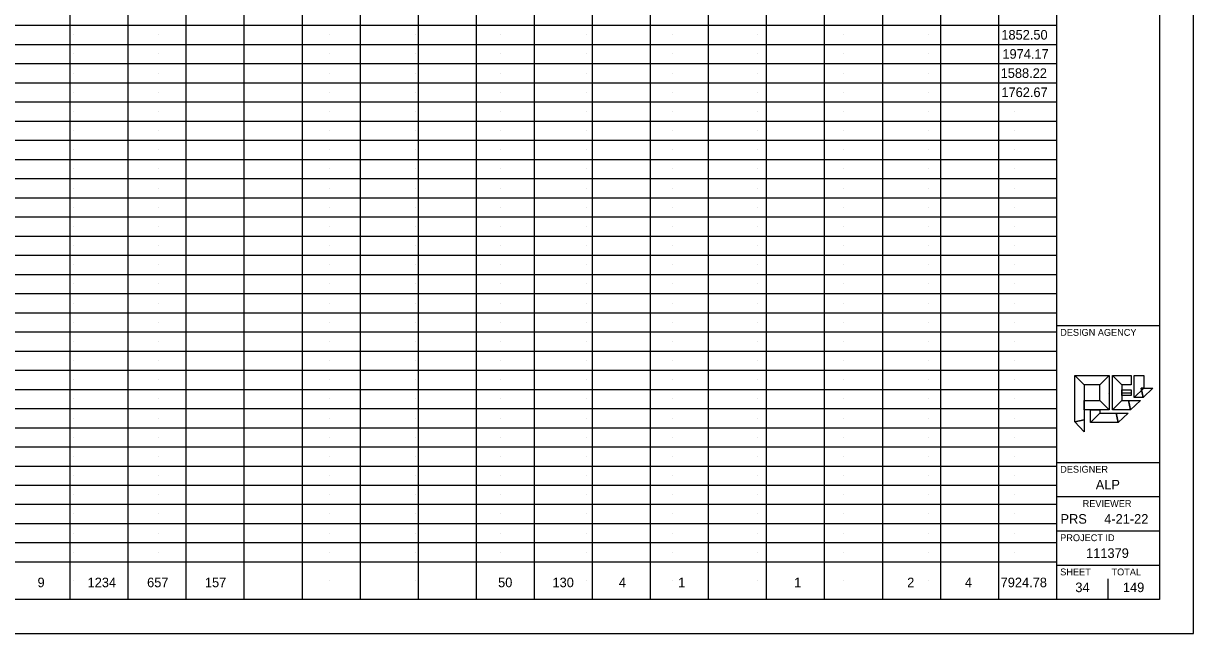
# Model space of a CAD drawing. Extents: x 2073163.9 to 2073197.9, y 634076.5 to 634098.5.
# Drawn here: x 2073180.84 to 2073197.95, y 634076.55 to 634085.46 of the extents above; entities that cross this region are included whole.
import ezdxf

# ---------------------------------------------------------------- set-up
doc = ezdxf.new("R2010")
doc.units = 0
for name, color, linetype in [('Default', 7, 'Continuous'), ('SH_Border', 7, 'Continuous'), ('SH_Cut_Line', 7, 'Continuous'), ('SH_Data', 7, 'Continuous'), ('SH_Text', 7, 'Continuous')]:
    doc.layers.add(name, color=color, linetype=linetype)

msp = doc.modelspace()

# ---------------------------------------------------------------- linework, layer by layer
at = {"layer": 'Default'}
msp.add_line((2073196.896, 634080.068), (2073197.032, 634080.068), dxfattribs=at)
for points in [[(2073196.209, 634079.643), (2073196.209, 634080.32), (2073196.347, 634080.183), (2073196.347, 634079.671)], [(2073196.209, 634080.32), (2073196.712, 634080.32), (2073196.576, 634080.183), (2073196.347, 634080.183)], [(2073196.712, 634080.32), (2073196.712, 634079.817), (2073196.576, 634079.954), (2073196.576, 634080.183)], [(2073196.758, 634079.817), (2073196.758, 634080.32), (2073196.896, 634080.183), (2073196.896, 634079.954)], [(2073196.758, 634080.32), (2073197.032, 634080.32), (2073197.032, 634080.183), (2073196.896, 634080.183)], [(2073197.078, 634080), (2073197.078, 634080.32), (2073197.216, 634080.32), (2073197.216, 634080.137)], [(2073197.032, 634080.11), (2073197.032, 634080.026), (2073196.897, 634080.026), (2073196.897, 634080.11)], [(2073197.207, 634080), (2073197.078, 634080), (2073197.216, 634080.137), (2073197.179, 634080.137)], [(2073197.352, 634080.137), (2073197.207, 634080), (2073197.179, 634080.137)], [(2073196.712, 634079.817), (2073196.347, 634079.817), (2073196.347, 634079.954), (2073196.576, 634079.954)], [(2073197.024, 634079.817), (2073196.758, 634079.817), (2073196.896, 634079.954), (2073196.996, 634079.954)], [(2073197.169, 634079.954), (2073197.024, 634079.817), (2073196.996, 634079.954)], [(2073196.347, 634079.497), (2073196.209, 634079.643), (2073196.347, 634079.671)], [(2073196.438, 634079.634), (2073196.438, 634079.817), (2073196.576, 634079.817), (2073196.576, 634079.771)], [(2073196.841, 634079.634), (2073196.438, 634079.634), (2073196.576, 634079.771), (2073196.812, 634079.771)], [(2073196.987, 634079.771), (2073196.841, 634079.634), (2073196.812, 634079.771)]]:
    msp.add_lwpolyline(points, close=True, dxfattribs=at)
at = {"layer": 'SH_Border'}
for p, q in [((2073195.946, 634077.05), (2073195.946, 634098.05)), ((2073195.946, 634081.05), (2073197.446, 634081.05)), ((2073195.946, 634079.05), (2073197.446, 634079.05)), ((2073195.946, 634078.55), (2073197.446, 634078.55)), ((2073195.946, 634078.05), (2073197.446, 634078.05)), ((2073195.946, 634077.55), (2073197.446, 634077.55))]:
    msp.add_line(p, q, dxfattribs=at)
msp.add_lwpolyline([(2073165.446, 634098.05), (2073197.446, 634098.05), (2073197.446, 634077.05), (2073165.446, 634077.05)], close=True, dxfattribs=at)
at = {"layer": 'SH_Cut_Line'}
msp.add_lwpolyline([(2073163.946, 634076.55), (2073197.946, 634076.55), (2073197.946, 634098.55), (2073163.946, 634098.55)], close=True, dxfattribs=at)
at = {"layer": 'SH_Data'}
for p, q in [((2073165.446, 634085.438), (2073195.946, 634085.438)), ((2073165.446, 634085.158), (2073195.946, 634085.158)), ((2073181.571, 634085.298), (2073181.571, 634085.298)), ((2073182.821, 634085.298), (2073182.821, 634085.298)), ((2073184.071, 634085.298), (2073184.071, 634085.298)), ((2073185.321, 634085.298), (2073185.321, 634085.298)), ((2073186.571, 634085.298), (2073186.571, 634085.298)), ((2073187.821, 634085.298), (2073187.821, 634085.298)), ((2073189.071, 634085.298), (2073189.071, 634085.298)), ((2073190.321, 634085.298), (2073190.321, 634085.298)), ((2073191.571, 634085.298), (2073191.571, 634085.298)), ((2073192.821, 634085.298), (2073192.821, 634085.298)), ((2073194.071, 634085.298), (2073194.071, 634085.298)), ((2073195.321, 634085.298), (2073195.321, 634085.298)), ((2073181.571, 634085.018), (2073181.571, 634085.018)), ((2073182.821, 634085.018), (2073182.821, 634085.018)), ((2073184.071, 634085.018), (2073184.071, 634085.018)), ((2073185.321, 634085.018), (2073185.321, 634085.018)), ((2073186.571, 634085.018), (2073186.571, 634085.018)), ((2073187.821, 634085.018), (2073187.821, 634085.018)), ((2073189.071, 634085.018), (2073189.071, 634085.018)), ((2073190.321, 634085.018), (2073190.321, 634085.018)), ((2073191.571, 634085.018), (2073191.571, 634085.018)), ((2073192.821, 634085.018), (2073192.821, 634085.018)), ((2073194.071, 634085.018), (2073194.071, 634085.018)), ((2073195.321, 634085.018), (2073195.321, 634085.018)), ((2073165.446, 634084.878), (2073195.946, 634084.878)), ((2073181.571, 634084.738), (2073181.571, 634084.738)), ((2073182.821, 634084.738), (2073182.821, 634084.738)), ((2073184.071, 634084.738), (2073184.071, 634084.738)), ((2073185.321, 634084.738), (2073185.321, 634084.738)), ((2073186.571, 634084.738), (2073186.571, 634084.738)), ((2073187.821, 634084.738), (2073187.821, 634084.738)), ((2073189.071, 634084.738), (2073189.071, 634084.738)), ((2073190.321, 634084.738), (2073190.321, 634084.738)), ((2073191.571, 634084.738), (2073191.571, 634084.738)), ((2073192.821, 634084.738), (2073192.821, 634084.738)), ((2073194.071, 634084.738), (2073194.071, 634084.738)), ((2073195.321, 634084.738), (2073195.321, 634084.738)), ((2073165.446, 634084.598), (2073195.946, 634084.598)), ((2073181.571, 634084.458), (2073181.571, 634084.458)), ((2073182.821, 634084.458), (2073182.821, 634084.458)), ((2073184.071, 634084.458), (2073184.071, 634084.458)), ((2073185.321, 634084.458), (2073185.321, 634084.458)), ((2073186.571, 634084.458), (2073186.571, 634084.458)), ((2073187.821, 634084.458), (2073187.821, 634084.458)), ((2073189.071, 634084.458), (2073189.071, 634084.458)), ((2073190.321, 634084.458), (2073190.321, 634084.458)), ((2073191.571, 634084.458), (2073191.571, 634084.458)), ((2073192.821, 634084.458), (2073192.821, 634084.458)), ((2073194.071, 634084.458), (2073194.071, 634084.458)), ((2073195.321, 634084.458), (2073195.321, 634084.458)), ((2073165.446, 634084.318), (2073195.946, 634084.318)), ((2073181.571, 634084.178), (2073181.571, 634084.178)), ((2073182.821, 634084.178), (2073182.821, 634084.178)), ((2073184.071, 634084.178), (2073184.071, 634084.178)), ((2073185.321, 634084.178), (2073185.321, 634084.178)), ((2073186.571, 634084.178), (2073186.571, 634084.178)), ((2073187.821, 634084.178), (2073187.821, 634084.178)), ((2073189.071, 634084.178), (2073189.071, 634084.178)), ((2073190.321, 634084.178), (2073190.321, 634084.178)), ((2073191.571, 634084.178), (2073191.571, 634084.178)), ((2073192.821, 634084.178), (2073192.821, 634084.178)), ((2073194.071, 634084.178), (2073194.071, 634084.178)), ((2073195.321, 634084.178), (2073195.321, 634084.178)), ((2073165.446, 634084.038), (2073195.946, 634084.038)), ((2073181.571, 634083.898), (2073181.571, 634083.898)), ((2073182.821, 634083.898), (2073182.821, 634083.898)), ((2073184.071, 634083.898), (2073184.071, 634083.898)), ((2073185.321, 634083.898), (2073185.321, 634083.898)), ((2073186.571, 634083.898), (2073186.571, 634083.898)), ((2073187.821, 634083.898), (2073187.821, 634083.898)), ((2073189.071, 634083.898), (2073189.071, 634083.898)), ((2073190.321, 634083.898), (2073190.321, 634083.898)), ((2073191.571, 634083.898), (2073191.571, 634083.898)), ((2073192.821, 634083.898), (2073192.821, 634083.898)), ((2073194.071, 634083.898), (2073194.071, 634083.898)), ((2073195.321, 634083.898), (2073195.321, 634083.898)), ((2073165.446, 634083.758), (2073195.946, 634083.758)), ((2073181.571, 634083.618), (2073181.571, 634083.618)), ((2073182.821, 634083.618), (2073182.821, 634083.618)), ((2073184.071, 634083.618), (2073184.071, 634083.618)), ((2073185.321, 634083.618), (2073185.321, 634083.618)), ((2073186.571, 634083.618), (2073186.571, 634083.618)), ((2073187.821, 634083.618), (2073187.821, 634083.618)), ((2073189.071, 634083.618), (2073189.071, 634083.618)), ((2073190.321, 634083.618), (2073190.321, 634083.618)), ((2073191.571, 634083.618), (2073191.571, 634083.618)), ((2073192.821, 634083.618), (2073192.821, 634083.618)), ((2073194.071, 634083.618), (2073194.071, 634083.618)), ((2073195.321, 634083.618), (2073195.321, 634083.618)), ((2073165.446, 634083.478), (2073195.946, 634083.478)), ((2073181.571, 634083.338), (2073181.571, 634083.338)), ((2073182.821, 634083.338), (2073182.821, 634083.338)), ((2073184.071, 634083.338), (2073184.071, 634083.338)), ((2073185.321, 634083.338), (2073185.321, 634083.338)), ((2073186.571, 634083.338), (2073186.571, 634083.338)), ((2073187.821, 634083.338), (2073187.821, 634083.338)), ((2073189.071, 634083.338), (2073189.071, 634083.338)), ((2073190.321, 634083.338), (2073190.321, 634083.338)), ((2073191.571, 634083.338), (2073191.571, 634083.338)), ((2073192.821, 634083.338), (2073192.821, 634083.338)), ((2073194.071, 634083.338), (2073194.071, 634083.338)), ((2073195.321, 634083.338), (2073195.321, 634083.338)), ((2073165.446, 634083.198), (2073195.946, 634083.198)), ((2073165.446, 634082.918), (2073195.946, 634082.918)), ((2073181.571, 634083.058), (2073181.571, 634083.058)), ((2073182.821, 634083.058), (2073182.821, 634083.058)), ((2073184.071, 634083.058), (2073184.071, 634083.058)), ((2073185.321, 634083.058), (2073185.321, 634083.058)), ((2073186.571, 634083.058), (2073186.571, 634083.058)), ((2073187.821, 634083.058), (2073187.821, 634083.058)), ((2073189.071, 634083.058), (2073189.071, 634083.058)), ((2073190.321, 634083.058), (2073190.321, 634083.058)), ((2073191.571, 634083.058), (2073191.571, 634083.058)), ((2073192.821, 634083.058), (2073192.821, 634083.058)), ((2073194.071, 634083.058), (2073194.071, 634083.058)), ((2073195.321, 634083.058), (2073195.321, 634083.058)), ((2073181.571, 634082.778), (2073181.571, 634082.778)), ((2073182.821, 634082.778), (2073182.821, 634082.778)), ((2073184.071, 634082.778), (2073184.071, 634082.778)), ((2073185.321, 634082.778), (2073185.321, 634082.778)), ((2073186.571, 634082.778), (2073186.571, 634082.778)), ((2073187.821, 634082.778), (2073187.821, 634082.778)), ((2073189.071, 634082.778), (2073189.071, 634082.778)), ((2073190.321, 634082.778), (2073190.321, 634082.778)), ((2073191.571, 634082.778), (2073191.571, 634082.778)), ((2073192.821, 634082.778), (2073192.821, 634082.778)), ((2073194.071, 634082.778), (2073194.071, 634082.778)), ((2073195.321, 634082.778), (2073195.321, 634082.778)), ((2073165.446, 634082.638), (2073195.946, 634082.638)), ((2073181.571, 634082.498), (2073181.571, 634082.498)), ((2073182.821, 634082.498), (2073182.821, 634082.498)), ((2073184.071, 634082.498), (2073184.071, 634082.498)), ((2073185.321, 634082.498), (2073185.321, 634082.498)), ((2073186.571, 634082.498), (2073186.571, 634082.498)), ((2073187.821, 634082.498), (2073187.821, 634082.498)), ((2073189.071, 634082.498), (2073189.071, 634082.498)), ((2073190.321, 634082.498), (2073190.321, 634082.498)), ((2073191.571, 634082.498), (2073191.571, 634082.498)), ((2073192.821, 634082.498), (2073192.821, 634082.498)), ((2073194.071, 634082.498), (2073194.071, 634082.498)), ((2073195.321, 634082.498), (2073195.321, 634082.498)), ((2073165.446, 634082.358), (2073195.946, 634082.358)), ((2073165.446, 634082.078), (2073195.946, 634082.078)), ((2073181.571, 634082.218), (2073181.571, 634082.218)), ((2073182.821, 634082.218), (2073182.821, 634082.218)), ((2073184.071, 634082.218), (2073184.071, 634082.218)), ((2073185.321, 634082.218), (2073185.321, 634082.218)), ((2073186.571, 634082.218), (2073186.571, 634082.218)), ((2073187.821, 634082.218), (2073187.821, 634082.218)), ((2073189.071, 634082.218), (2073189.071, 634082.218)), ((2073190.321, 634082.218), (2073190.321, 634082.218)), ((2073191.571, 634082.218), (2073191.571, 634082.218)), ((2073192.821, 634082.218), (2073192.821, 634082.218)), ((2073194.071, 634082.218), (2073194.071, 634082.218)), ((2073195.321, 634082.218), (2073195.321, 634082.218)), ((2073181.571, 634081.938), (2073181.571, 634081.938)), ((2073182.821, 634081.938), (2073182.821, 634081.938)), ((2073184.071, 634081.938), (2073184.071, 634081.938)), ((2073185.321, 634081.938), (2073185.321, 634081.938)), ((2073186.571, 634081.938), (2073186.571, 634081.938)), ((2073187.821, 634081.938), (2073187.821, 634081.938)), ((2073189.071, 634081.938), (2073189.071, 634081.938)), ((2073190.321, 634081.938), (2073190.321, 634081.938)), ((2073191.571, 634081.938), (2073191.571, 634081.938)), ((2073192.821, 634081.938), (2073192.821, 634081.938)), ((2073194.071, 634081.938), (2073194.071, 634081.938)), ((2073195.321, 634081.938), (2073195.321, 634081.938)), ((2073165.446, 634081.798), (2073195.946, 634081.798)), ((2073181.571, 634081.658), (2073181.571, 634081.658)), ((2073182.821, 634081.658), (2073182.821, 634081.658)), ((2073184.071, 634081.658), (2073184.071, 634081.658)), ((2073185.321, 634081.658), (2073185.321, 634081.658)), ((2073186.571, 634081.658), (2073186.571, 634081.658)), ((2073187.821, 634081.658), (2073187.821, 634081.658)), ((2073189.071, 634081.658), (2073189.071, 634081.658)), ((2073190.321, 634081.658), (2073190.321, 634081.658)), ((2073191.571, 634081.658), (2073191.571, 634081.658)), ((2073192.821, 634081.658), (2073192.821, 634081.658)), ((2073194.071, 634081.658), (2073194.071, 634081.658)), ((2073195.321, 634081.658), (2073195.321, 634081.658)), ((2073165.446, 634081.518), (2073195.946, 634081.518)), ((2073165.446, 634081.238), (2073195.946, 634081.238)), ((2073181.571, 634081.378), (2073181.571, 634081.378)), ((2073182.821, 634081.378), (2073182.821, 634081.378)), ((2073184.071, 634081.378), (2073184.071, 634081.378)), ((2073185.321, 634081.378), (2073185.321, 634081.378)), ((2073186.571, 634081.378), (2073186.571, 634081.378)), ((2073187.821, 634081.378), (2073187.821, 634081.378)), ((2073189.071, 634081.378), (2073189.071, 634081.378)), ((2073190.321, 634081.378), (2073190.321, 634081.378)), ((2073191.571, 634081.378), (2073191.571, 634081.378)), ((2073192.821, 634081.378), (2073192.821, 634081.378)), ((2073194.071, 634081.378), (2073194.071, 634081.378)), ((2073195.321, 634081.378), (2073195.321, 634081.378)), ((2073181.571, 634081.098), (2073181.571, 634081.098)), ((2073182.821, 634081.098), (2073182.821, 634081.098)), ((2073184.071, 634081.098), (2073184.071, 634081.098)), ((2073185.321, 634081.098), (2073185.321, 634081.098)), ((2073186.571, 634081.098), (2073186.571, 634081.098)), ((2073187.821, 634081.098), (2073187.821, 634081.098)), ((2073189.071, 634081.098), (2073189.071, 634081.098)), ((2073190.321, 634081.098), (2073190.321, 634081.098)), ((2073191.571, 634081.098), (2073191.571, 634081.098)), ((2073192.821, 634081.098), (2073192.821, 634081.098)), ((2073194.071, 634081.098), (2073194.071, 634081.098)), ((2073195.321, 634081.098), (2073195.321, 634081.098)), ((2073165.446, 634080.958), (2073195.946, 634080.958)), ((2073181.571, 634080.818), (2073181.571, 634080.818)), ((2073182.821, 634080.818), (2073182.821, 634080.818)), ((2073184.071, 634080.818), (2073184.071, 634080.818)), ((2073185.321, 634080.818), (2073185.321, 634080.818)), ((2073186.571, 634080.818), (2073186.571, 634080.818)), ((2073187.821, 634080.818), (2073187.821, 634080.818)), ((2073189.071, 634080.818), (2073189.071, 634080.818)), ((2073190.321, 634080.818), (2073190.321, 634080.818)), ((2073191.571, 634080.818), (2073191.571, 634080.818)), ((2073192.821, 634080.818), (2073192.821, 634080.818)), ((2073194.071, 634080.818), (2073194.071, 634080.818)), ((2073195.321, 634080.818), (2073195.321, 634080.818)), ((2073165.446, 634080.678), (2073195.946, 634080.678)), ((2073181.571, 634080.538), (2073181.571, 634080.538)), ((2073182.821, 634080.538), (2073182.821, 634080.538)), ((2073184.071, 634080.538), (2073184.071, 634080.538)), ((2073185.321, 634080.538), (2073185.321, 634080.538)), ((2073186.571, 634080.538), (2073186.571, 634080.538)), ((2073187.821, 634080.538), (2073187.821, 634080.538)), ((2073189.071, 634080.538), (2073189.071, 634080.538)), ((2073190.321, 634080.538), (2073190.321, 634080.538)), ((2073191.571, 634080.538), (2073191.571, 634080.538)), ((2073192.821, 634080.538), (2073192.821, 634080.538)), ((2073194.071, 634080.538), (2073194.071, 634080.538)), ((2073195.321, 634080.538), (2073195.321, 634080.538)), ((2073165.446, 634080.398), (2073195.946, 634080.398)), ((2073181.571, 634080.258), (2073181.571, 634080.258)), ((2073182.821, 634080.258), (2073182.821, 634080.258)), ((2073184.071, 634080.258), (2073184.071, 634080.258)), ((2073185.321, 634080.258), (2073185.321, 634080.258)), ((2073186.571, 634080.258), (2073186.571, 634080.258)), ((2073187.821, 634080.258), (2073187.821, 634080.258)), ((2073189.071, 634080.258), (2073189.071, 634080.258)), ((2073190.321, 634080.258), (2073190.321, 634080.258)), ((2073191.571, 634080.258), (2073191.571, 634080.258)), ((2073192.821, 634080.258), (2073192.821, 634080.258)), ((2073194.071, 634080.258), (2073194.071, 634080.258)), ((2073195.321, 634080.258), (2073195.321, 634080.258)), ((2073165.446, 634080.118), (2073195.946, 634080.118)), ((2073196.696, 634080.05), (2073196.696, 634080.05)), ((2073181.571, 634079.978), (2073181.571, 634079.978)), ((2073182.821, 634079.978), (2073182.821, 634079.978)), ((2073184.071, 634079.978), (2073184.071, 634079.978)), ((2073185.321, 634079.978), (2073185.321, 634079.978)), ((2073186.571, 634079.978), (2073186.571, 634079.978)), ((2073187.821, 634079.978), (2073187.821, 634079.978)), ((2073189.071, 634079.978), (2073189.071, 634079.978)), ((2073190.321, 634079.978), (2073190.321, 634079.978)), ((2073191.571, 634079.978), (2073191.571, 634079.978)), ((2073192.821, 634079.978), (2073192.821, 634079.978)), ((2073194.071, 634079.978), (2073194.071, 634079.978)), ((2073195.321, 634079.978), (2073195.321, 634079.978)), ((2073165.446, 634079.838), (2073195.946, 634079.838)), ((2073181.571, 634079.698), (2073181.571, 634079.698)), ((2073182.821, 634079.698), (2073182.821, 634079.698)), ((2073184.071, 634079.698), (2073184.071, 634079.698)), ((2073185.321, 634079.698), (2073185.321, 634079.698)), ((2073186.571, 634079.698), (2073186.571, 634079.698)), ((2073187.821, 634079.698), (2073187.821, 634079.698)), ((2073189.071, 634079.698), (2073189.071, 634079.698)), ((2073190.321, 634079.698), (2073190.321, 634079.698)), ((2073191.571, 634079.698), (2073191.571, 634079.698)), ((2073192.821, 634079.698), (2073192.821, 634079.698)), ((2073194.071, 634079.698), (2073194.071, 634079.698)), ((2073195.321, 634079.698), (2073195.321, 634079.698)), ((2073165.446, 634079.558), (2073195.946, 634079.558)), ((2073196.783, 634079.64), (2073196.783, 634079.64)), ((2073181.571, 634079.418), (2073181.571, 634079.418)), ((2073182.821, 634079.418), (2073182.821, 634079.418)), ((2073184.071, 634079.418), (2073184.071, 634079.418)), ((2073185.321, 634079.418), (2073185.321, 634079.418)), ((2073186.571, 634079.418), (2073186.571, 634079.418)), ((2073187.821, 634079.418), (2073187.821, 634079.418)), ((2073189.071, 634079.418), (2073189.071, 634079.418)), ((2073190.321, 634079.418), (2073190.321, 634079.418)), ((2073191.571, 634079.418), (2073191.571, 634079.418)), ((2073192.821, 634079.418), (2073192.821, 634079.418)), ((2073194.071, 634079.418), (2073194.071, 634079.418)), ((2073195.321, 634079.418), (2073195.321, 634079.418)), ((2073165.446, 634079.278), (2073195.946, 634079.278)), ((2073165.446, 634078.998), (2073195.946, 634078.998)), ((2073181.571, 634079.138), (2073181.571, 634079.138)), ((2073182.821, 634079.138), (2073182.821, 634079.138)), ((2073184.071, 634079.138), (2073184.071, 634079.138)), ((2073185.321, 634079.138), (2073185.321, 634079.138)), ((2073186.571, 634079.138), (2073186.571, 634079.138)), ((2073187.821, 634079.138), (2073187.821, 634079.138)), ((2073189.071, 634079.138), (2073189.071, 634079.138)), ((2073190.321, 634079.138), (2073190.321, 634079.138)), ((2073191.571, 634079.138), (2073191.571, 634079.138)), ((2073192.821, 634079.138), (2073192.821, 634079.138)), ((2073194.071, 634079.138), (2073194.071, 634079.138)), ((2073195.321, 634079.138), (2073195.321, 634079.138)), ((2073181.571, 634078.858), (2073181.571, 634078.858)), ((2073182.821, 634078.858), (2073182.821, 634078.858)), ((2073184.071, 634078.858), (2073184.071, 634078.858)), ((2073185.321, 634078.858), (2073185.321, 634078.858)), ((2073186.571, 634078.858), (2073186.571, 634078.858)), ((2073187.821, 634078.858), (2073187.821, 634078.858)), ((2073189.071, 634078.858), (2073189.071, 634078.858)), ((2073190.321, 634078.858), (2073190.321, 634078.858)), ((2073191.571, 634078.858), (2073191.571, 634078.858)), ((2073192.821, 634078.858), (2073192.821, 634078.858)), ((2073194.071, 634078.858), (2073194.071, 634078.858)), ((2073195.321, 634078.858), (2073195.321, 634078.858)), ((2073165.446, 634078.718), (2073195.946, 634078.718)), ((2073181.571, 634078.578), (2073181.571, 634078.578)), ((2073182.821, 634078.578), (2073182.821, 634078.578)), ((2073184.071, 634078.578), (2073184.071, 634078.578)), ((2073185.321, 634078.578), (2073185.321, 634078.578)), ((2073186.571, 634078.578), (2073186.571, 634078.578)), ((2073187.821, 634078.578), (2073187.821, 634078.578)), ((2073189.071, 634078.578), (2073189.071, 634078.578)), ((2073190.321, 634078.578), (2073190.321, 634078.578)), ((2073191.571, 634078.578), (2073191.571, 634078.578)), ((2073192.821, 634078.578), (2073192.821, 634078.578)), ((2073194.071, 634078.578), (2073194.071, 634078.578)), ((2073195.321, 634078.578), (2073195.321, 634078.578)), ((2073165.446, 634078.438), (2073195.946, 634078.438)), ((2073165.446, 634078.158), (2073195.946, 634078.158)), ((2073181.571, 634078.298), (2073181.571, 634078.298)), ((2073182.821, 634078.298), (2073182.821, 634078.298)), ((2073184.071, 634078.298), (2073184.071, 634078.298)), ((2073185.321, 634078.298), (2073185.321, 634078.298)), ((2073186.571, 634078.298), (2073186.571, 634078.298)), ((2073187.821, 634078.298), (2073187.821, 634078.298)), ((2073189.071, 634078.298), (2073189.071, 634078.298)), ((2073190.321, 634078.298), (2073190.321, 634078.298)), ((2073191.571, 634078.298), (2073191.571, 634078.298)), ((2073192.821, 634078.298), (2073192.821, 634078.298)), ((2073194.071, 634078.298), (2073194.071, 634078.298)), ((2073195.321, 634078.298), (2073195.321, 634078.298)), ((2073181.571, 634078.018), (2073181.571, 634078.018)), ((2073182.821, 634078.018), (2073182.821, 634078.018)), ((2073184.071, 634078.018), (2073184.071, 634078.018)), ((2073185.321, 634078.018), (2073185.321, 634078.018)), ((2073186.571, 634078.018), (2073186.571, 634078.018)), ((2073187.821, 634078.018), (2073187.821, 634078.018)), ((2073189.071, 634078.018), (2073189.071, 634078.018)), ((2073190.321, 634078.018), (2073190.321, 634078.018)), ((2073191.571, 634078.018), (2073191.571, 634078.018)), ((2073192.821, 634078.018), (2073192.821, 634078.018)), ((2073194.071, 634078.018), (2073194.071, 634078.018)), ((2073195.321, 634078.018), (2073195.321, 634078.018)), ((2073165.446, 634077.878), (2073195.946, 634077.878)), ((2073181.571, 634077.738), (2073181.571, 634077.738)), ((2073182.821, 634077.738), (2073182.821, 634077.738)), ((2073184.071, 634077.738), (2073184.071, 634077.738)), ((2073185.321, 634077.738), (2073185.321, 634077.738)), ((2073186.571, 634077.738), (2073186.571, 634077.738)), ((2073187.821, 634077.738), (2073187.821, 634077.738)), ((2073189.071, 634077.738), (2073189.071, 634077.738)), ((2073190.321, 634077.738), (2073190.321, 634077.738)), ((2073191.571, 634077.738), (2073191.571, 634077.738)), ((2073192.821, 634077.738), (2073192.821, 634077.738)), ((2073194.071, 634077.738), (2073194.071, 634077.738)), ((2073195.321, 634077.738), (2073195.321, 634077.738)), ((2073165.446, 634077.598), (2073195.946, 634077.598)), ((2073181.571, 634077.324), (2073181.571, 634077.324)), ((2073182.821, 634077.324), (2073182.821, 634077.324)), ((2073184.071, 634077.324), (2073184.071, 634077.324)), ((2073185.321, 634077.324), (2073185.321, 634077.324)), ((2073186.571, 634077.324), (2073186.571, 634077.324)), ((2073187.821, 634077.324), (2073187.821, 634077.324)), ((2073189.071, 634077.324), (2073189.071, 634077.324)), ((2073190.321, 634077.324), (2073190.321, 634077.324)), ((2073191.571, 634077.324), (2073191.571, 634077.324)), ((2073192.821, 634077.324), (2073192.821, 634077.324)), ((2073194.071, 634077.324), (2073194.071, 634077.324)), ((2073195.321, 634077.324), (2073195.321, 634077.324)), ((2073196.696, 634077.05), (2073196.696, 634077.35)), ((2073196.321, 634077.225), (2073196.321, 634077.225))]:
    msp.add_line(p, q, dxfattribs=at)
at = {"layer": 'SH_Text'}
for p, q in [((2073195.097, 634077.05), (2073195.097, 634098.05)), ((2073181.525, 634077.05), (2073181.525, 634097.77)), ((2073182.373, 634077.05), (2073182.373, 634097.77)), ((2073183.221, 634077.05), (2073183.221, 634097.77)), ((2073184.069, 634077.05), (2073184.069, 634097.77)), ((2073184.918, 634077.05), (2073184.918, 634097.77)), ((2073185.766, 634077.05), (2073185.766, 634097.77)), ((2073186.614, 634077.05), (2073186.614, 634097.77)), ((2073187.463, 634077.05), (2073187.463, 634097.77)), ((2073188.311, 634077.05), (2073188.311, 634097.77)), ((2073189.159, 634077.05), (2073189.159, 634097.77)), ((2073190.008, 634077.05), (2073190.008, 634097.77)), ((2073190.856, 634077.05), (2073190.856, 634097.77)), ((2073191.704, 634077.05), (2073191.704, 634097.77)), ((2073192.552, 634077.05), (2073192.552, 634097.77)), ((2073193.401, 634077.05), (2073193.401, 634097.77)), ((2073194.249, 634077.05), (2073194.249, 634097.77))]:
    msp.add_line(p, q, dxfattribs=at)

# ---------------------------------------------------------------- texts
at = {"layer": 'Default'}
for s, p in [('ALP', (2073196.515, 634078.655)), ('PRS', (2073196, 634078.155)), ('4-21-22', (2073196.639, 634078.155)), ('111379', (2073196.374, 634077.655)), ('34', (2073196.217, 634077.155)), ('149', (2073196.912, 634077.155))]:
    msp.add_text(s, height=0.14, rotation=360, dxfattribs=at).set_placement(p)
at = {"layer": 'SH_Data'}
for s, p in [('DESIGN AGENCY', (2073195.996, 634080.9)), ('DESIGNER', (2073195.996, 634078.9)), ('REVIEWER', (2073196.324, 634078.4)), ('PROJECT ID', (2073195.996, 634077.9)), ('SHEET', (2073195.996, 634077.4)), ('TOTAL', (2073196.746, 634077.4))]:
    msp.add_text(s, height=0.1, rotation=360, dxfattribs=at).set_placement(p)
at = {"layer": 'SH_Text'}
for s, p in [('1852.50', (2073195.135, 634085.228)), ('1974.17', (2073195.151, 634084.948)), ('1588.22', (2073195.125, 634084.668)), ('1762.67', (2073195.136, 634084.388)), ('9', (2073181.046, 634077.227)), ('1234', (2073181.778, 634077.227)), ('657', (2073182.648, 634077.227)), ('157', (2073183.493, 634077.227)), ('50', (2073187.779, 634077.227)), ('130', (2073188.574, 634077.227)), ('4', (2073189.544, 634077.227)), ('1', (2073190.411, 634077.227)), ('1', (2073192.107, 634077.227)), ('2', (2073193.759, 634077.227)), ('4', (2073194.603, 634077.227)), ('7924.78', (2073195.125, 634077.227))]:
    msp.add_text(s, height=0.14, rotation=0.0001, dxfattribs=at).set_placement(p)

doc.saveas('drawing.dxf')
